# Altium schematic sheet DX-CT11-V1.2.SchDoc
size 840 x 594 mm; SheetNumber: 1; SheetTotal: 1
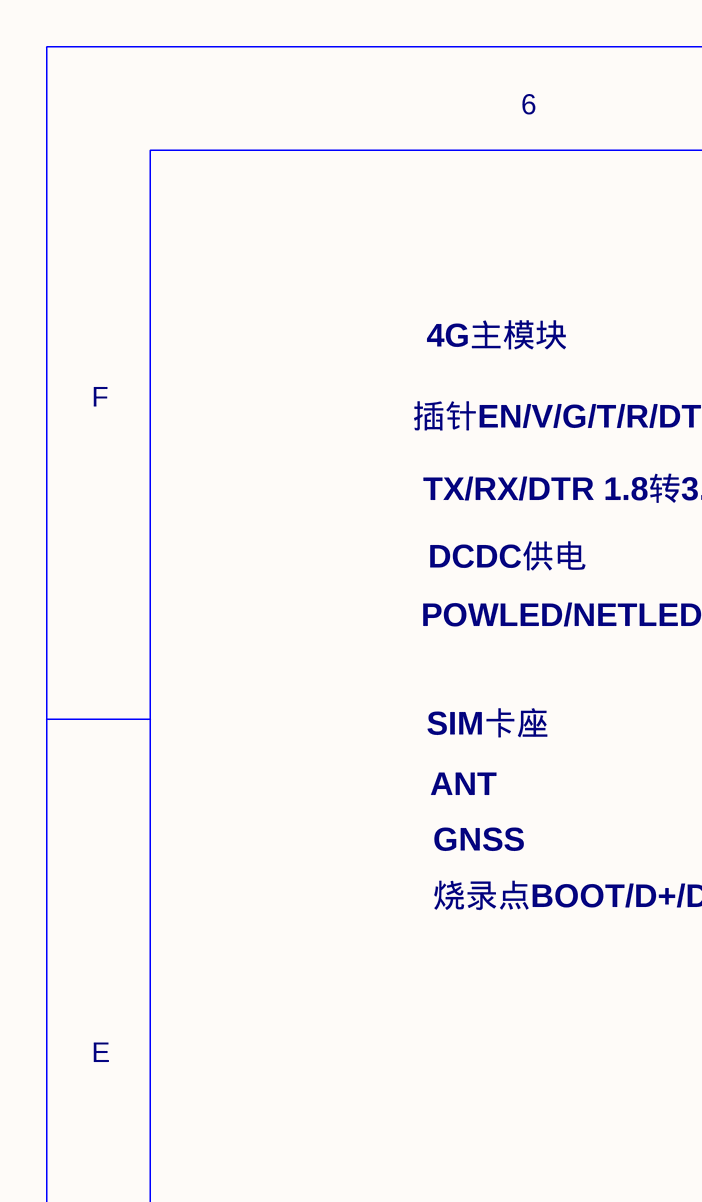
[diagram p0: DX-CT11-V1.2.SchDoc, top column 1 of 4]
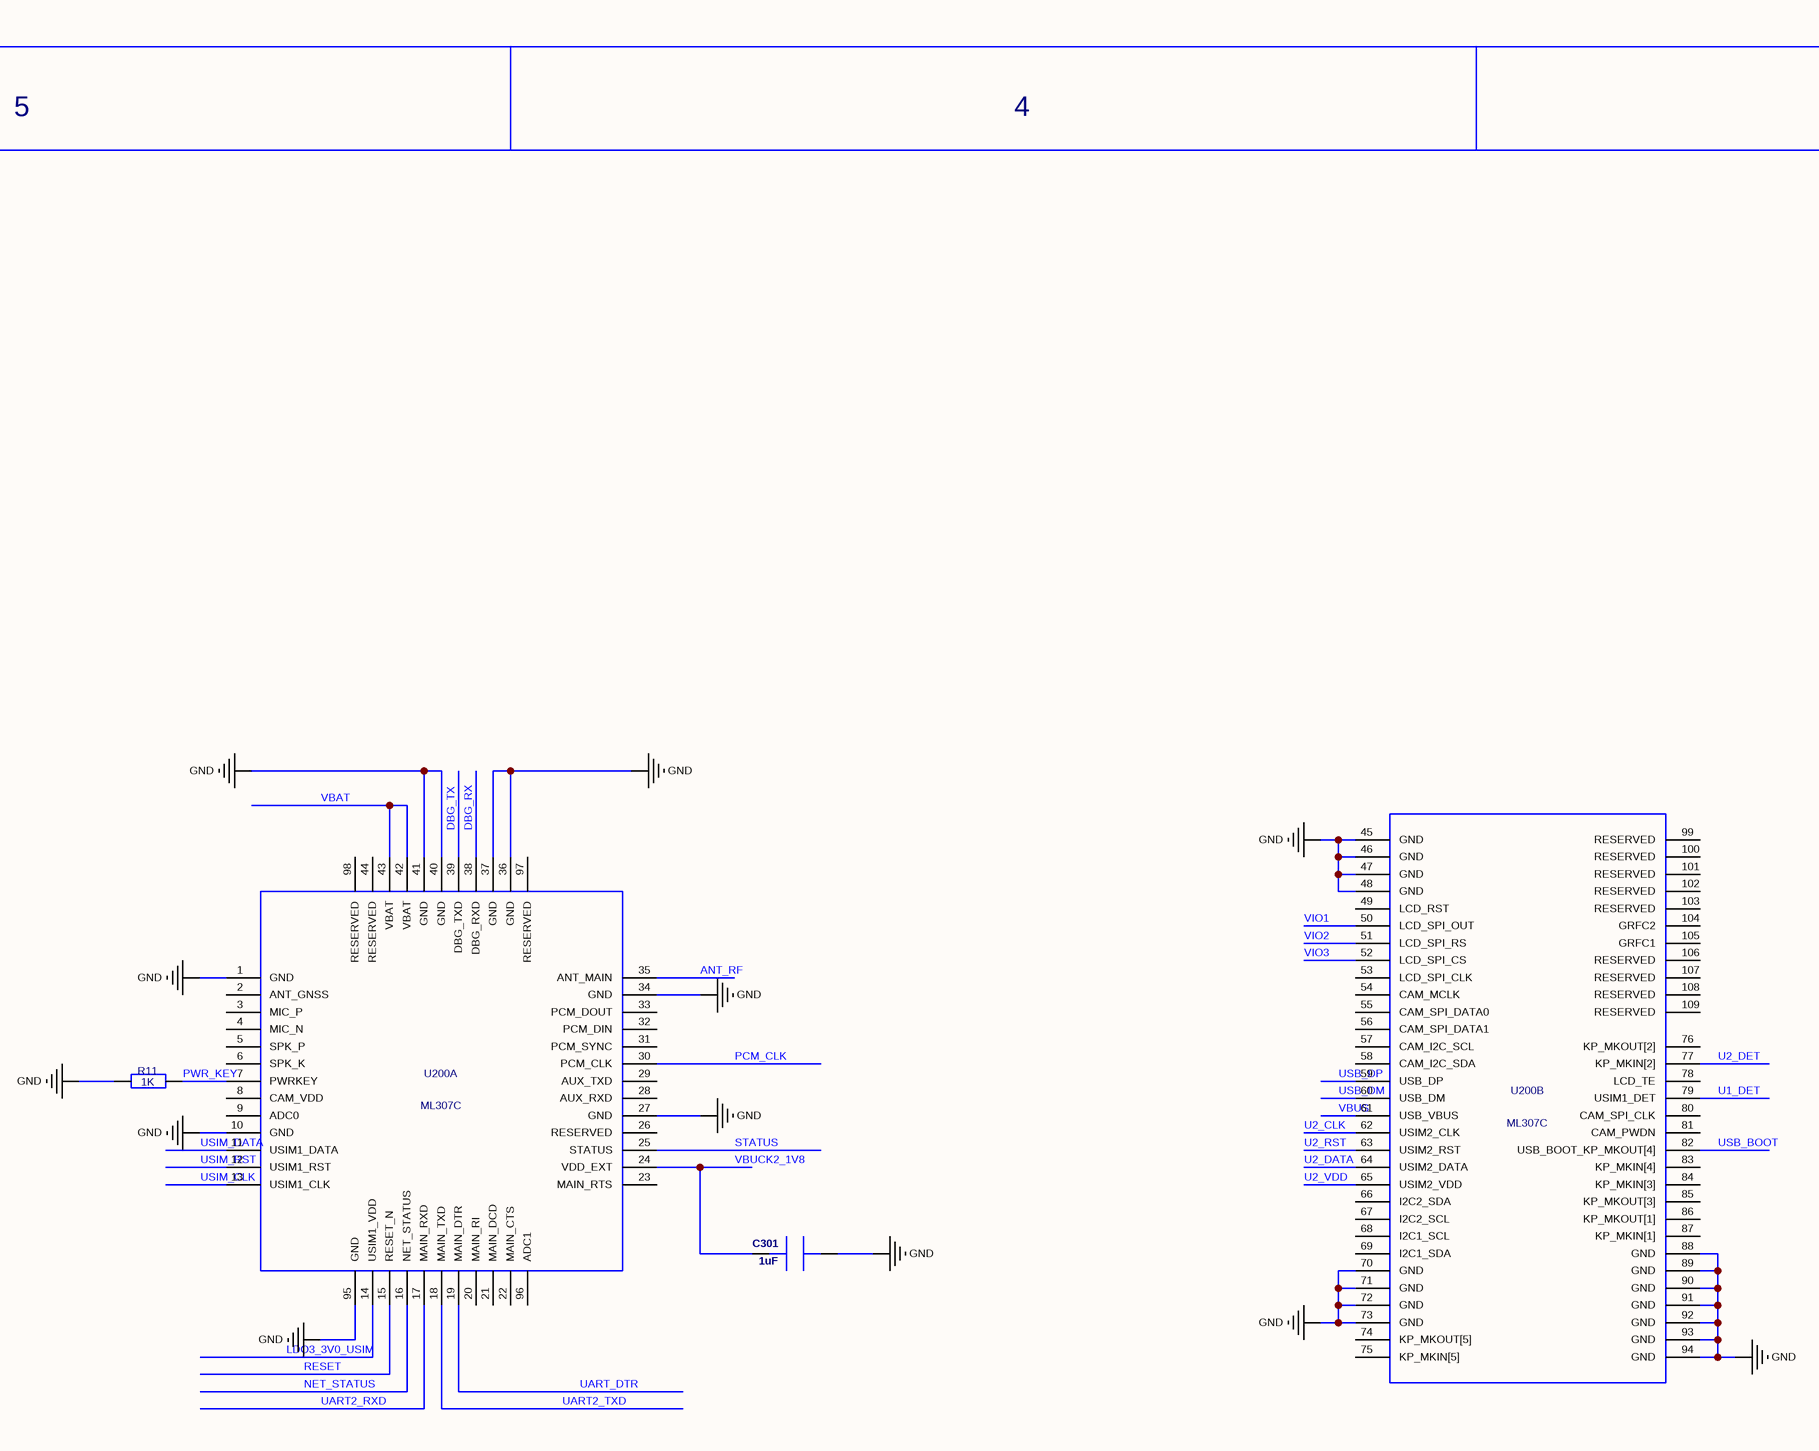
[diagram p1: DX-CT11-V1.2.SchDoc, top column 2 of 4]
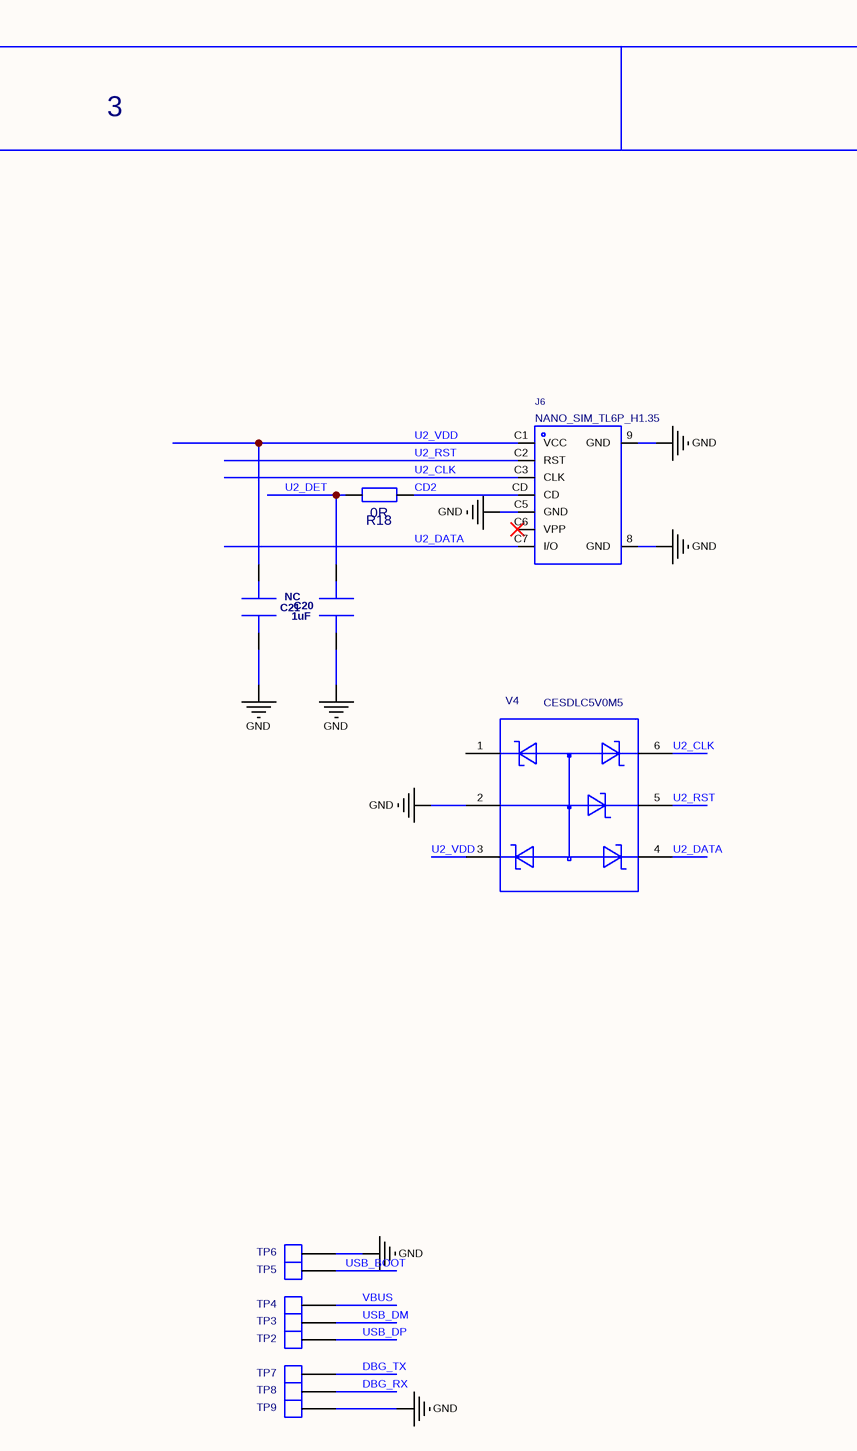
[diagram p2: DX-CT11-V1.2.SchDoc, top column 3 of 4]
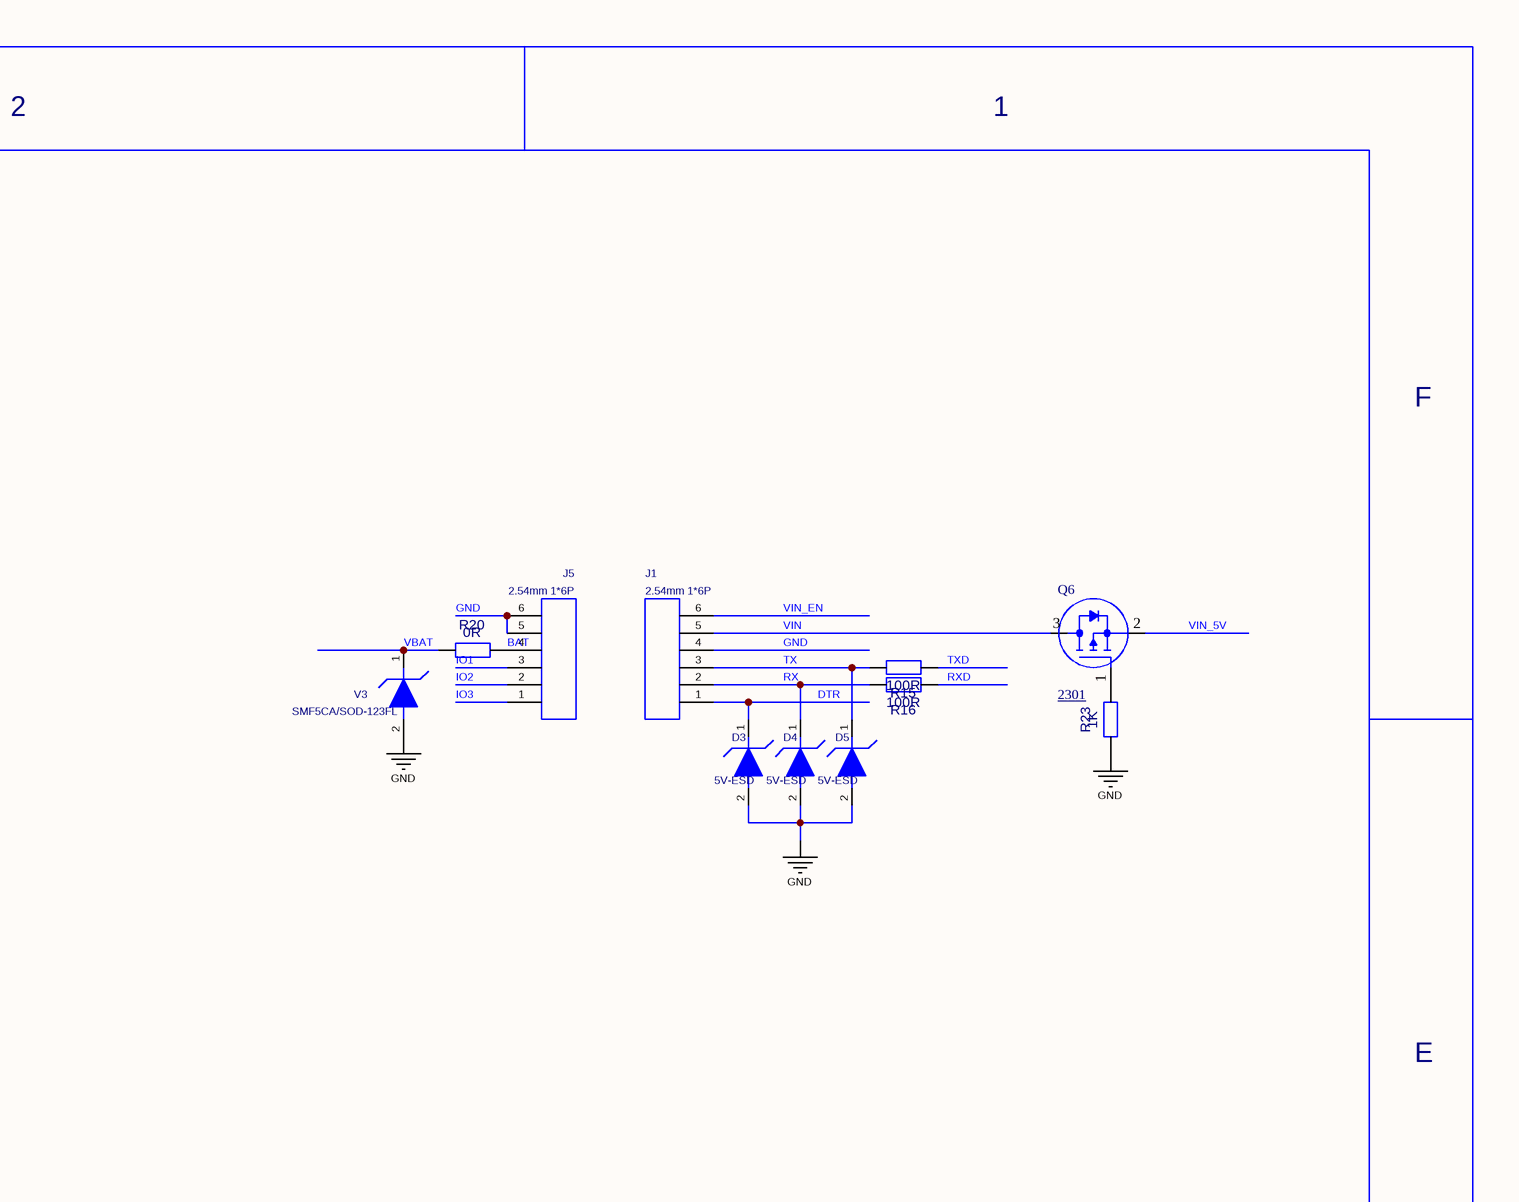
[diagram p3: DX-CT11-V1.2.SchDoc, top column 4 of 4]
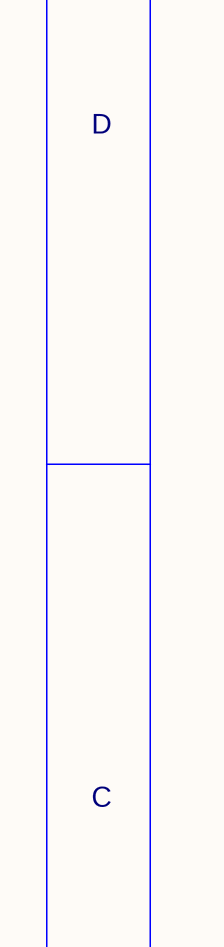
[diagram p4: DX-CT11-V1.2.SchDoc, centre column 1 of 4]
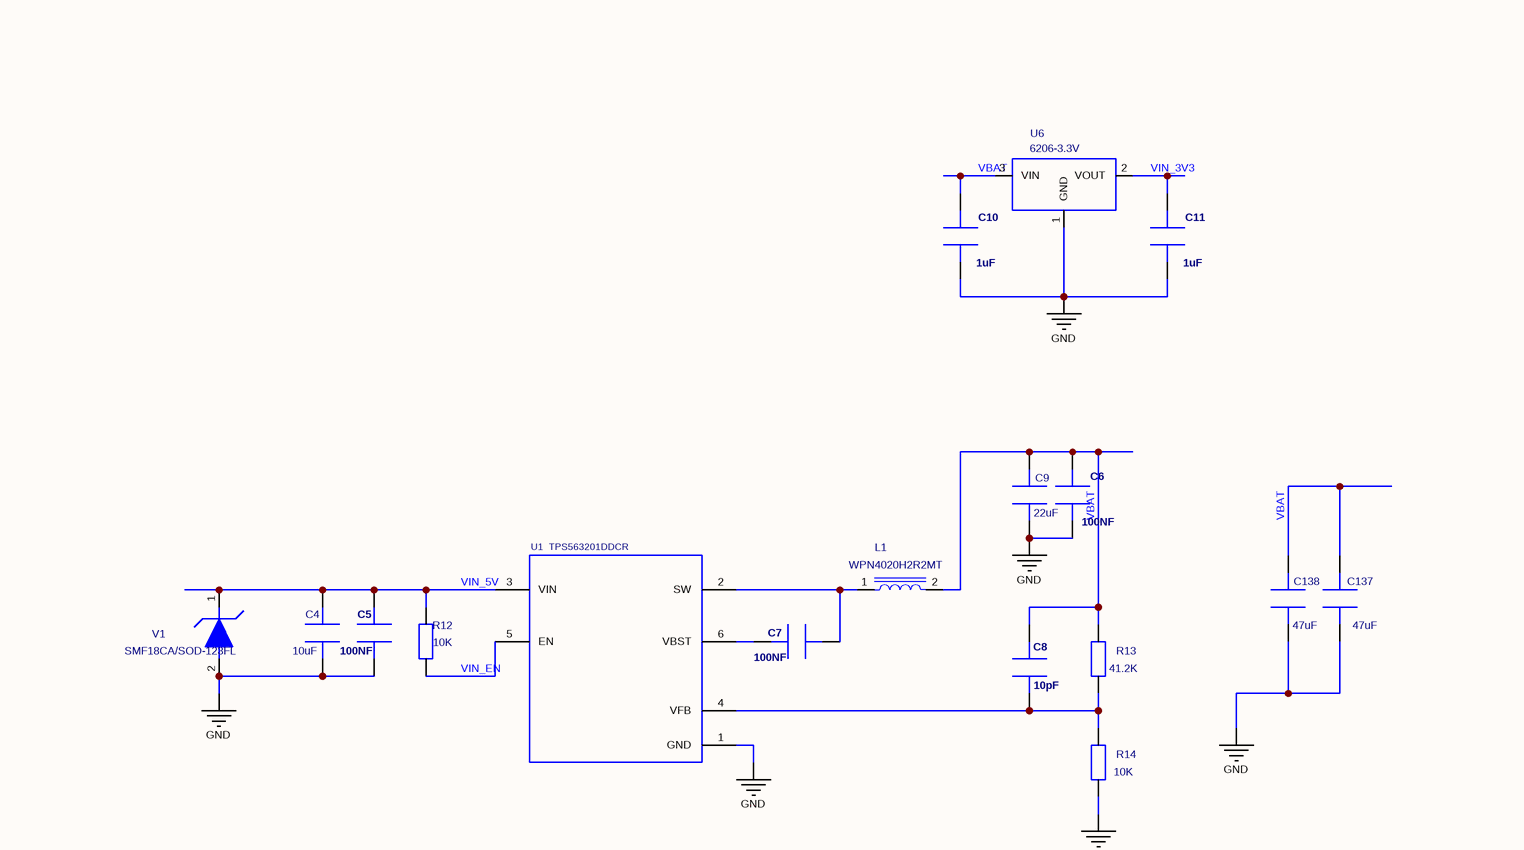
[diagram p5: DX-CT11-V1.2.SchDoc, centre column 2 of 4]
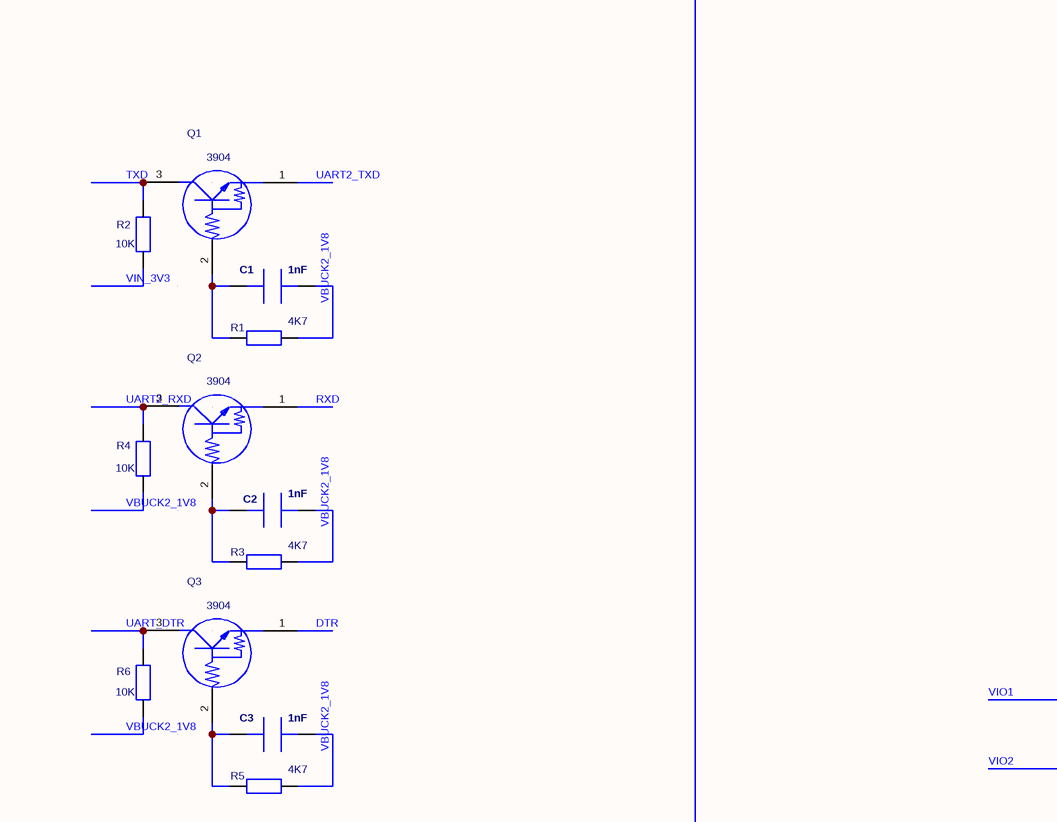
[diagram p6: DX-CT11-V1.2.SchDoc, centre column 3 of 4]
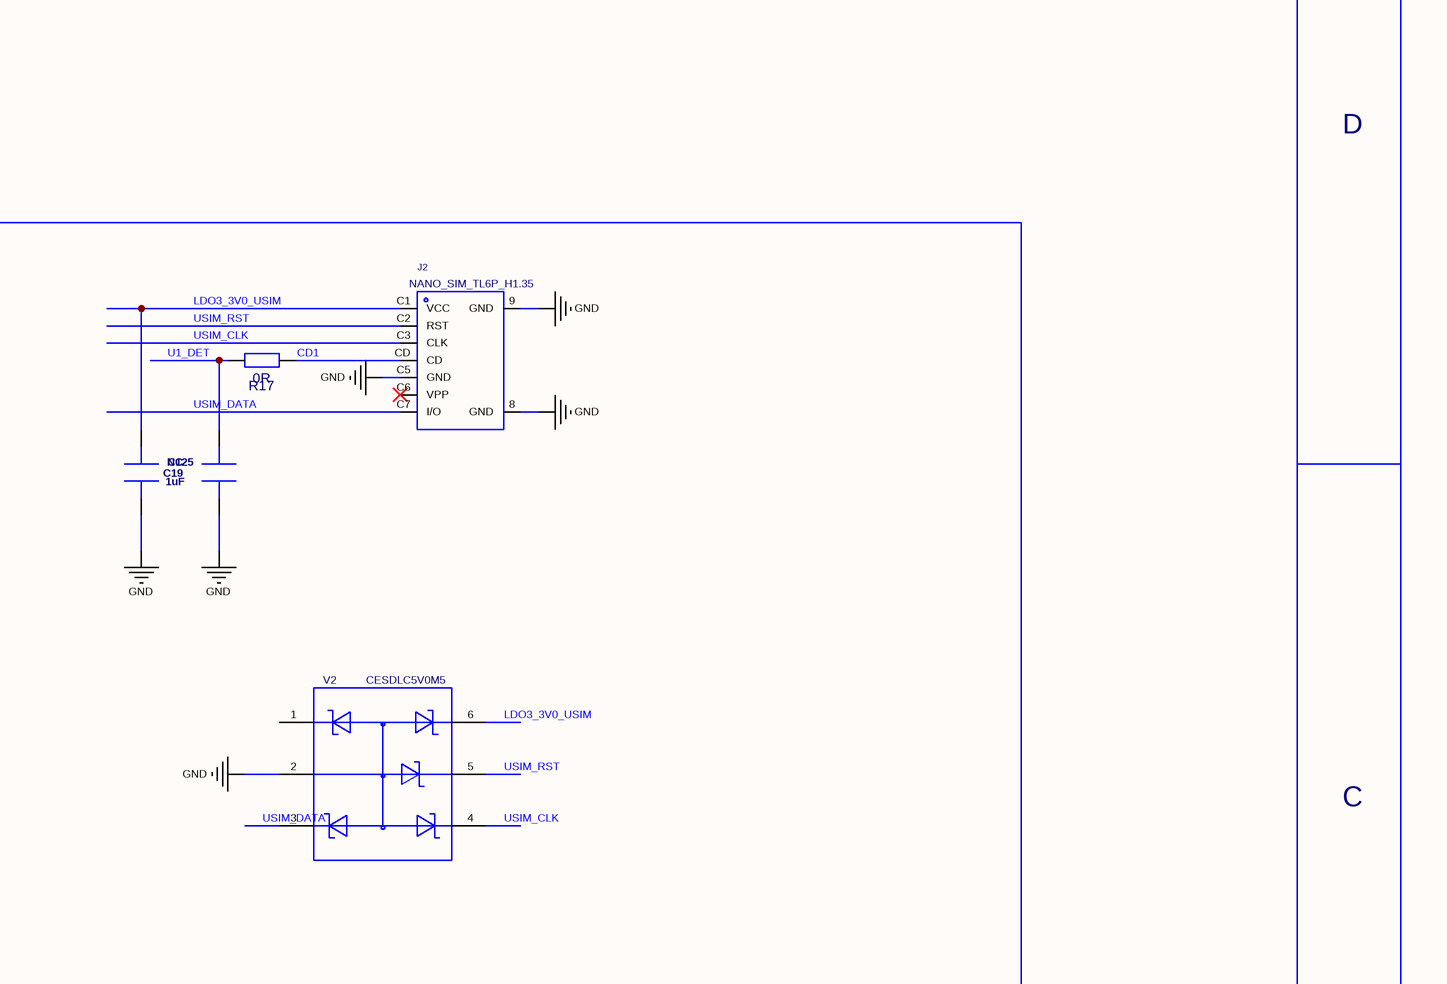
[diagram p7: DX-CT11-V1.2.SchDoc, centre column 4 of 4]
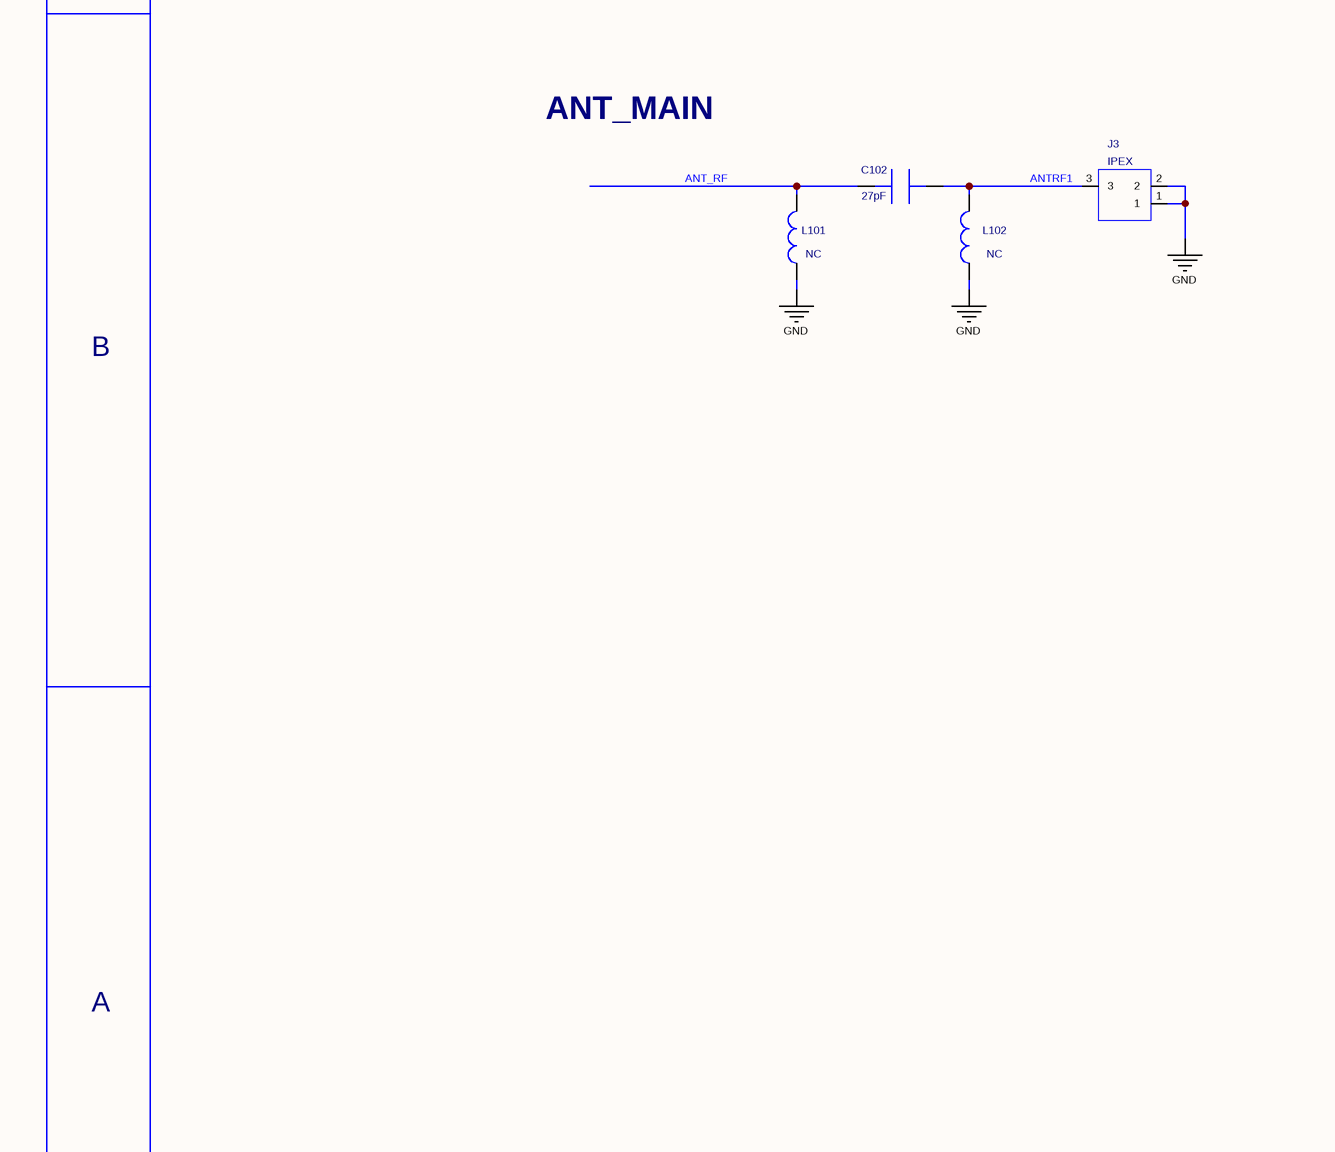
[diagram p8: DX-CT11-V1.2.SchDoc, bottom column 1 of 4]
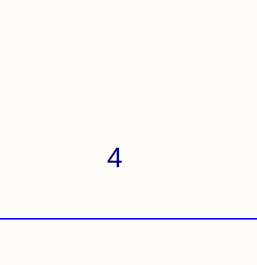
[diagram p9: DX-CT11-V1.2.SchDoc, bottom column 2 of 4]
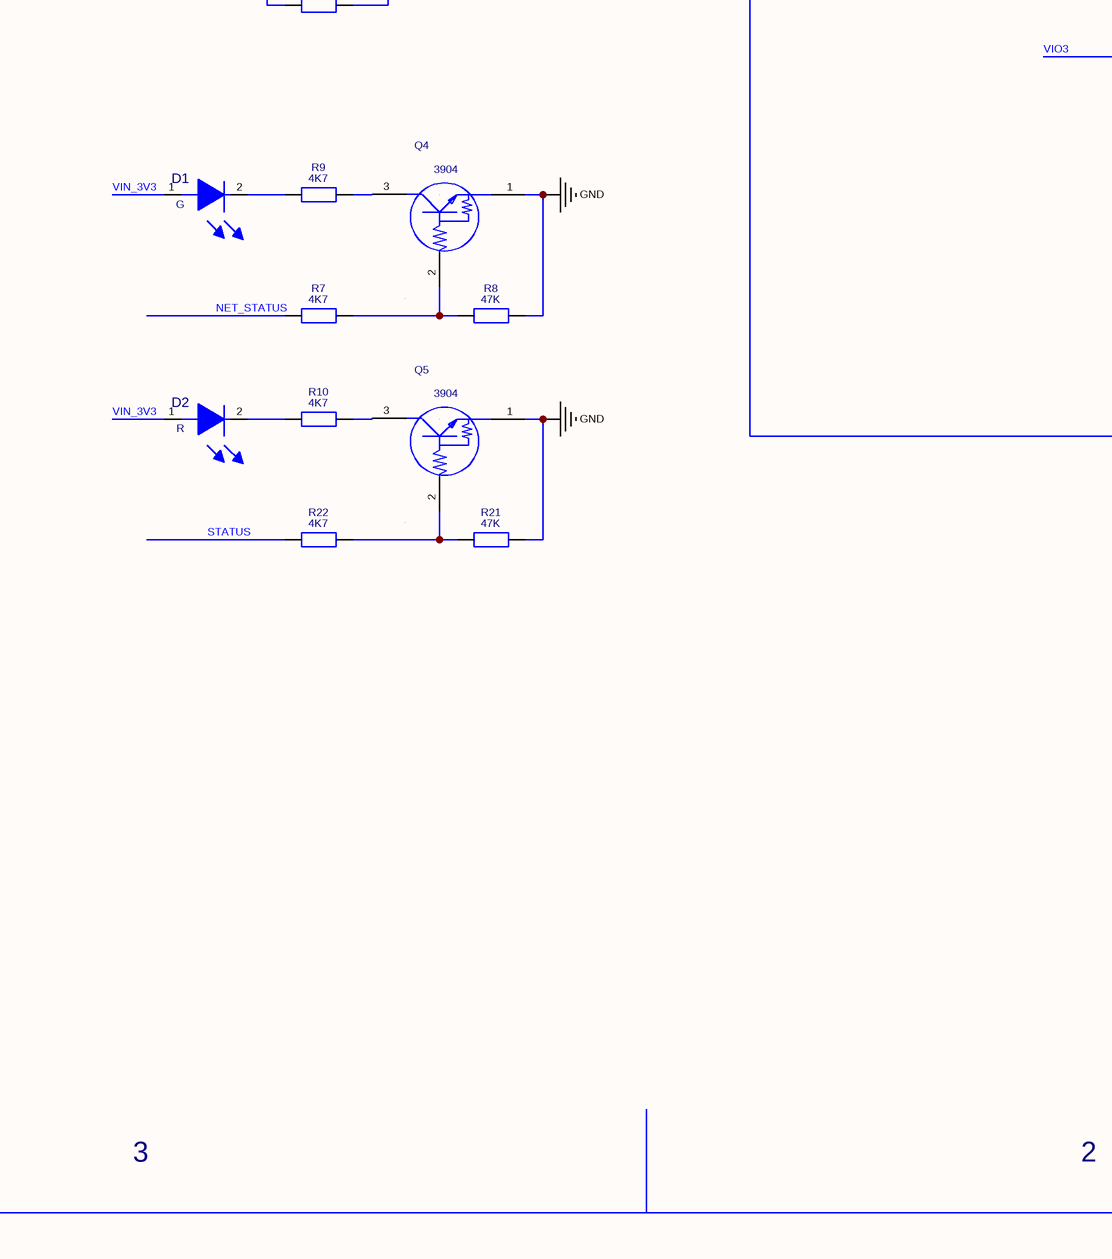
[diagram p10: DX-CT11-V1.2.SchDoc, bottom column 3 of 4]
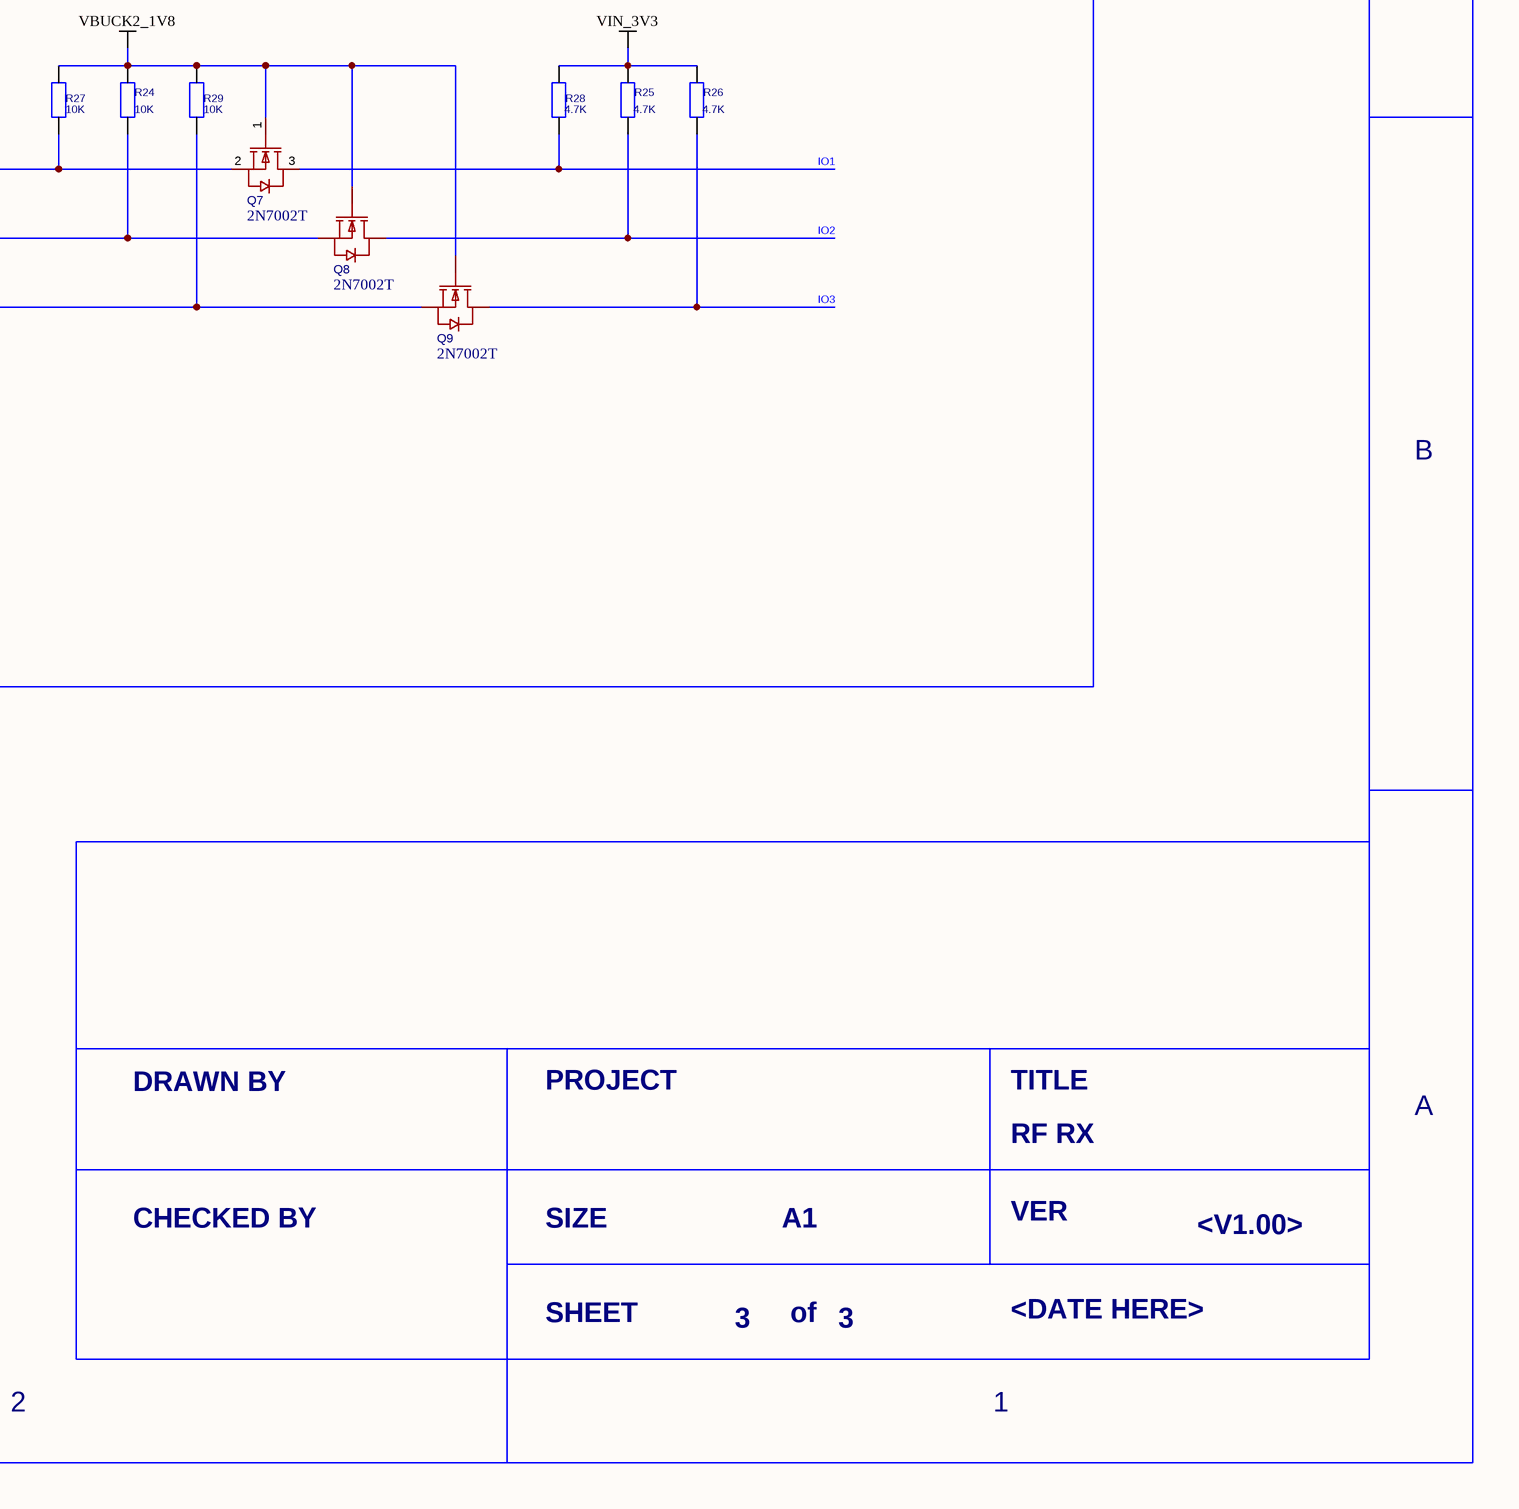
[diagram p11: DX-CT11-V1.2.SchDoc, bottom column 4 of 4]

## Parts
C1  1nF  [SMD0402]
C2  1nF  [SMD0402]
C3  1nF  [SMD0402]
C4  10uF  [SMD0805]
C5  100NF  [SMD0402]
C6  100NF  [SMD0402]
C7  100NF  [SMD0402]
C8  10pF  [SMD0402]
C9  22uF  [SMD0805]
C10  1uF  [SMD0402]
C11  1uF  [SMD0402]
C19  NC  [SMD0402]
C20  1uF  [SMD0402]
C21  NC  [SMD0402]
C102  27pF  [SMD0402]
C125  1uF  [SMD0402]
C137  47uF  [C1206L]
C138  47uF  [C1206L]
C301  1uF  [SMD0402]
D1  G  [LED_0603]
D2  R  [LED_0603]
D3  5V-ESD  [SMD0402_ESD_TVS]
D4  5V-ESD  [SMD0402_ESD_TVS]
D5  5V-ESD  [SMD0402_ESD_TVS]
J1  2.54mm 1*6P  [254-6]
J2  NANO_SIM_TL6P_H1.35  [nanosim_]
J3  IPEX  [IPEX]
J5  2.54mm 1*6P  [254-6]
J6  NANO_SIM_TL6P_H1.35  [nanosim_]
L1  WPN4020H2R2MT  [WPN4020H]
L101  NC  [SMD0402]
L102  NC  [SMD0402]
Q1  3904  [EMT3]
Q2  3904  [EMT3]
Q3  3904  [EMT3]
Q4  3904  [EMT3]
Q5  3904  [EMT3]
Q6  2301  [SOT-23-3_L2.9-W1.3-P1.90-LS2.4-BR]
Q7  2N7002T  [SC-75-3_L1.6-W0.8-P1.00-LS1.7-BR]
Q8  2N7002T  [SC-75-3_L1.6-W0.8-P1.00-LS1.7-BR]
Q9  2N7002T  [SC-75-3_L1.6-W0.8-P1.00-LS1.7-BR]
R1  4K7  [SMD0402]
R2  10K  [SMD0402]
R3  4K7  [SMD0402]
R4  10K  [SMD0402]
R5  4K7  [SMD0402]
R6  10K  [SMD0402]
R7  4K7  [SMD0402]
R8  47K  [SMD0402]
R9  4K7  [SMD0402]
R10  4K7  [SMD0402]
R11  1K  [SMD0402]
R12  10K  [SMD0402]
R13  41.2K  [SMD0402]
R14  10K  [SMD0402]
R15  100R  [SMD0402]
R16  100R  [SMD0402]
R17  0R  [SMD0402]
R18  0R  [SMD0402]
R20  0R  [SMD0805]
R21  47K  [SMD0402]
R22  4K7  [SMD0402]
R23  1K  [SMD0402]
R24  10K  [SMD0402]
R25  4.7K  [SMD0402]
R26  4.7K  [SMD0402]
R27  10K  [SMD0402]
R28  4.7K  [SMD0402]
R29  10K  [SMD0402]
TP2  TP2  [TP-0.8X1.6]
TP3  TP3  [TP-0.8X1.6]
TP4  TP4  [TP-0.8X1.6]
TP5  TP5  [TP-0.8X1.6]
TP6  TP6  [TP-0.8X1.6]
TP7  TP7  [TP-0.8X1.6]
TP8  TP8  [TP-0.8X1.6]
TP9  TP9  [TP-0.8X1.6]
U1  TPS563201DDCR  [DDC0006A_L]
U6  6206-3.3V  [SOT23-3P95_280X110L60X40L]
U200  ML307C  [L511-1]  (parts A,B of 2)
V1  SMF18CA/SOD-123FL  [SOD123FL]
V2  CESDLC5V0M5  [SOT-563_L1.6-W1.2-P0.50-LS1.6-BR]
V3  SMF5CA/SOD-123FL  [SOD123FL]
V4  CESDLC5V0M5  [SOT-563_L1.6-W1.2-P0.50-LS1.6-BR]

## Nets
GND: C4.1 C5.1 C6.1 C9.1 C10.1 C11.1 C19.2 C20.1 C21.2 C125.1 C137.1 C138.1 C301.1 D3.2(+) D4.2(+) D5.2(+) J1.4 J2.8(GND) J2.9(GND) J2.C5(GND) J3.1 J3.2 J5.5 J5.6 J6.8(GND) J6.9(GND) J6.C5(GND) L101.2 L102.2 Q4.1 Q5.1 R8.1 R11.2 R14.2 R21.1 R23.2 TP6.1 TP9.1 U1.1(GND) U6.1(GND) U200.1(GND) U200.10(GND) U200.27(GND) U200.34(GND) U200.36(GND) U200.37(GND) U200.40(GND) U200.41(GND) U200.45(GND) U200.46(GND) U200.47(GND) U200.48(GND) U200.70(GND) U200.71(GND) U200.72(GND) U200.73(GND) U200.88(GND) U200.89(GND) U200.90(GND) U200.91(GND) U200.92(GND) U200.93(GND) U200.94(GND) U200.95(GND) V1.2(+) V2.2 V3.2(+) V4.2
VBUCK2_1V8: C1.2 C2.2 C3.2 C301.2 Q7.1(G) Q8.1(G) Q9.1(G) R1.1 R3.1 R4.2 R5.1 R6.2 R24.1 R27.2 R29.1 U200.24(VDD_EXT)
VIN_3V3: C11.2 D1.1 D2.1 R2.2 R25.1 R26.1 R28.2 U6.2(VOUT)
ANT_RF: C102.1 L101.1 U200.35(ANT_MAIN)
ANTRF1: C102.2 J3.3 L102.1
BAT: J5.4 R20.1
CD1: J2.CD R17.2
CD2: J6.CD R18.2
DBG_RX: TP8.1 U200.38(DBG_RXD)
DBG_TX: TP7.1 U200.39(DBG_TXD)
DTR: D3.1 J1.1 Q3.1
IO1: J5.3 Q7.3(D) R28.1
IO2: J5.2 Q8.3(D) R25.2
IO3: J5.1 Q9.3(D) R26.2
LDO3_3V0_USIM: C125.2 J2.C1(VCC) U200.14(USIM1_VDD) V2.6
NET_STATUS: R7.2 U200.16(NET_STATUS)
PCM_CLK: U200.30(PCM_CLK)
PWR_KEY: R11.1 U200.7(PWRKEY)
RESET: U200.15(RESET_N)
RX: D4.1 J1.2 R16.1
RXD: Q2.1 R16.2
STATUS: R22.2 U200.25(STATUS)
TX: D5.1 J1.3 R15.1
TXD: Q1.3 R2.1 R15.2
U1_DET: C19.1 R17.1 U200.79(USIM1_DET)
U2_CLK: J6.C3(CLK) U200.62(USIM2_CLK) V4.6
U2_DATA: J6.C7(I/O) U200.64(USIM2_DATA) V4.4
U2_DET: C21.1 R18.1 U200.77(KP_MKIN[2])
U2_RST: J6.C2(RST) U200.63(USIM2_RST) V4.5
U2_VDD: C20.2 J6.C1(VCC) U200.65(USIM2_VDD) V4.3
UART2_RXD: Q2.3 R4.1 U200.17(MAIN_RXD)
UART2_TXD: Q1.1 U200.18(MAIN_TXD)
UART_DTR: Q3.3 R6.1 U200.19(MAIN_DTR)
USB_BOOT: TP5.1 U200.82(USB_BOOT_KP_MKOUT[4])
USB_DM: TP3.1 U200.60(USB_DM)
USB_DP: TP2.1 U200.59(USB_DP)
USIM_CLK: J2.C3(CLK) U200.13(USIM1_CLK) V2.4
USIM_DATA: J2.C7(I/O) U200.11(USIM1_DATA) V2.3
USIM_RST: J2.C2(RST) U200.12(USIM1_RST) V2.5
VBAT: C6.2 C8.2 C9.2 C10.2 C137.2 C138.2 L1.2 R13.1 R20.2 U6.3(VIN) U200.42(VBAT) U200.43(VBAT) V3.1
VBUS: TP4.1 U200.61(USB_VBUS)
VIN: J1.5 Q6.3(D)
VIN_5V: C4.2 C5.2 Q6.2(S) R12.1 U1.3(VIN) V1.1
VIN_EN: J1.6 R12.2 U1.5(EN)
VIO1: Q7.2(S) R27.1 U200.50(LCD_SPI_OUT)
VIO2: Q8.2(S) R24.2 U200.51(LCD_SPI_RS)
VIO3: Q9.2(S) R29.2 U200.52(LCD_SPI_CS)
NetC1_1: C1.1 Q1.2 R1.2
NetC2_1: C2.1 Q2.2 R3.2
NetC3_1: C3.1 Q3.2 R5.2
NetC7_1: C7.1 L1.1 U1.2(SW)
NetC7_2: C7.2 U1.6(VBST)
NetC8_1: C8.1 R13.2 R14.1 U1.4(VFB)
NetD1_2: D1.2 R9.2
NetD2_2: D2.2 R10.2
NetQ4_2: Q4.2 R7.1 R8.2
NetQ4_3: Q4.3 R9.1
NetQ5_2: Q5.2 R21.2 R22.1
NetQ5_3: Q5.3 R10.1
NetQ6_1: Q6.1(G) R23.1

Not connected (* = marked no-connect by the designer): J2 C6(VPP)*; J6 C6(VPP)*; U200 2(ANT_GNSS) 3(MIC_P) 4(MIC_N) 5(SPK_P) 6(SPK_K) 8(CAM_VDD) 9(ADC0) 20(MAIN_RI) 21(MAIN_DCD) 22(MAIN_CTS) 23(MAIN_RTS) 26(RESERVED) 28(AUX_RXD) 29(AUX_TXD) 31(PCM_SYNC) 32(PCM_DIN) 33(PCM_DOUT) 44(RESERVED) 49(LCD_RST) 53(LCD_SPI_CLK) 54(CAM_MCLK) 55(CAM_SPI_DATA0) 56(CAM_SPI_DATA1) 57(CAM_I2C_SCL) 58(CAM_I2C_SDA) 66(I2C2_SDA) 67(I2C2_SCL) 68(I2C1_SCL) 69(I2C1_SDA) 74(KP_MKOUT[5]) 75(KP_MKIN[5]) 76(KP_MKOUT[2]) 78(LCD_TE) 80(CAM_SPI_CLK) 81(CAM_PWDN) 83(KP_MKIN[4]) 84(KP_MKIN[3]) 85(KP_MKOUT[3]) 86(KP_MKOUT[1]) 87(KP_MKIN[1]) 96(ADC1) 97(RESERVED) 98(RESERVED) 99(RESERVED) 100(RESERVED) 101(RESERVED) 102(RESERVED) 103(RESERVED) 104(GRFC2) 105(GRFC1) 106(RESERVED) 107(RESERVED) 108(RESERVED) 109(RESERVED); V2 1; V4 1

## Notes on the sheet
- 6
- 5
- 4
- 3
- 2
- 1
- F
- 4G主模块
- 插针EN/V/G/T/R/DTR
- TX/RX/DTR 1.8转3.3V
- DCDC供电
- POWLED/NETLED
- SIM卡座
- ANT
- GNSS
- 烧录点BOOT/D+/D-
- E
- D
- C
- ANT_MAIN
- B
- A
- DRAWN BY
- PROJECT
- TITLE
- RF RX
- CHECKED BY
- SIZE
- A1
- VER
- <V1.00>
- SHEET
- of
- <DATE HERE>

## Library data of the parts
C1-C3 C8 C10 C11 C20 C102 C125 C301 = CAP-0402: PART DESC: Bipolar Capacitor; PART NUMBER: 0402ZG104Z; Tolerance: +/-5%; Geometry.Height: 0.60000mm
C4 C9 C137 C138 = CAP-0805: Geometry.Height: 1.45000mm
C5 C7 = CAP-0402: PART DESC: Bipolar Capacitor; PART NUMBER: 0402ZG104Z; Tolerance: +/-5%; Value: 0.1uF; Geometry.Height: 0.60000mm
C6 C19 C21 = CAP-0402: PART DESC: Bipolar Capacitor; PART NUMBER: 0402ZG104Z; Tolerance: +/-5%; Value: 1uF; Geometry.Height: 0.60000mm
D1 = LED_0603: Geometry.Height: 0.50000mm
D2 = LED_0603: Value: G; Geometry.Height: 0.50000mm
D3-D5 = ESD-TVS-0402: Value: 5V 10P; Geometry.Height: 0.60000mm
J1 J5 = 254-6: Value: 2.54mm 1*6P直针/黄色
J2 J6 = NANO_SIM_TL6P_H1.35: Symbol: NANO SIM TL6P H1.35; Add_into_BOM: yes; Body_Height_(Max): 1.35mm; PCB DECAL: SIM-SMD_NANO-SIM-TL6P-H1.35; Value: NANO SIM TL6P H1.35
J3 = UFLR_0: Source_Path: F:\WORKSPACE\ALLEGRO16P6\LORA_PROJECT\LORA_ASR6601\ASR6601QFN48_MODULEBOARD\SCHEM\ASR6601QFN48_MODULE_V10_201030.DSN
L1 = INCT_1_L5: Source_Path: C:\USERS\ADMINISTRATOR\DESKTOP\222\OUT\PROJECT_WORKLIB.OLB
L101 L102 = IND-0402: Geometry.Height: 0.60000mm
Q1-Q5 = DTC123JETL: Value: 3904/SOT-523; Geometry.Height: 1.00000mm
Q6 = MOS-P: 1:G 2:D 3:S
R1-R8 R11 R12 R21-R24 = RES-0402: Geometry.Height: 0.60000mm
R9 R10 = RES-0402: Value: 2K2; Geometry.Height: 0.60000mm
R13 = RES-0402: Value: 41.2K1%; Geometry.Height: 0.60000mm
R14 = RES-0402: Value: 10K1%; Geometry.Height: 0.60000mm
R15-R18 = RES-0402: Value: 1K; Geometry.Height: 0.60000mm
R20 = RES-0402: PCB DECAL: SMD0402; Value: 1K; Geometry.Height: 0.60000mm
R25 R26 = RES-0402: Value: 10K; Geometry.Height: 0.60000mm
R27-R29 = RES-0402: Value: 4K7; Geometry.Height: 0.60000mm
TP2-TP9 = TP_C150A: test point on module; Value: NC; Geometry.Height: 0.05000mm
U1 = TPS563201DDCR: Mfr_Name: Texas Instruments
U6 = LDO
U200 = L511_BLGA: Geometry.Height: 2.4MM; Value: L511
V1 = ESD-TVS-0402: Geometry.Height: 0.60000mm
V2 V4 = CESDLC5V0M5: Breakdown_Voltage: 6.2V; Peak_Pulse_Current_(Ipp)@10/1000us: 2.5A; Maximum_Clamping_Voltage: 13V; Reverse_Stand_Off_Voltage_(Vrwm): 5V; Convert_to_PCB: yes
V3 = ESD-TVS-0402: Value: SMF18CA/SOD-123FL; Geometry.Height: 0.60000mm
